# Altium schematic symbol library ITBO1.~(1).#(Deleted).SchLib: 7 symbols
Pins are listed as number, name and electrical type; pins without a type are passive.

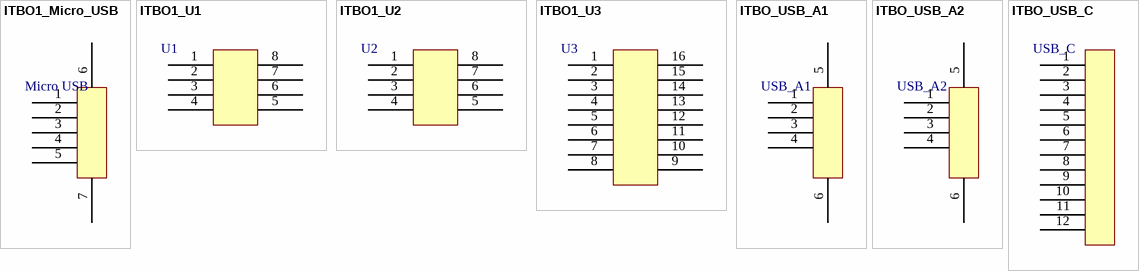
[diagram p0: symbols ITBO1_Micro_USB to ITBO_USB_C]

## ITBO1_Micro_USB
designator Micro USB  (value not drawn)
footprint MOLEX_1051330001
pins: 1, 2, 3, 4, 5, 6, 7

## ITBO1_U1
designator U1  (value not drawn)
footprint ITBO1_U1 (TSOP, 8-Leads, Body 4.85x3.85mm, Pitch 1.27mm, IPC Medium Density)
pins: 1, 2, 3, 4, 5, 6, 7, 8

## ITBO1_U2
designator U2  (value not drawn)
footprint ITBO1_U2 (TSOP, 8-Leads, Body 4.85x3.85mm, Pitch 1.27mm, IPC Medium Density)
pins: 1, 2, 3, 4, 5, 6, 7, 8

## ITBO1_U3
designator U3  (value not drawn)
footprint ITBO1_U3
pins: 1, 2, 3, 4, 5, 6, 7, 8, 9, 10, 11, 12, 13, 14, 15, 16

## ITBO_USB_A1
designator USB_A1  (value not drawn)
footprint MOLEX_48037-0001
pins: 1, 2, 3, 4, 5, 6

## ITBO_USB_A2
designator USB_A2  (value not drawn)
footprint MOLEX_48037-0001
pins: 1, 2, 3, 4, 5, 6

## ITBO_USB_C
designator USB_C  (value not drawn)
footprint MOLEX_105450-0101
pins: 1, 2, 3, 4, 5, 6, 7, 8, 9, 10, 11, 12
